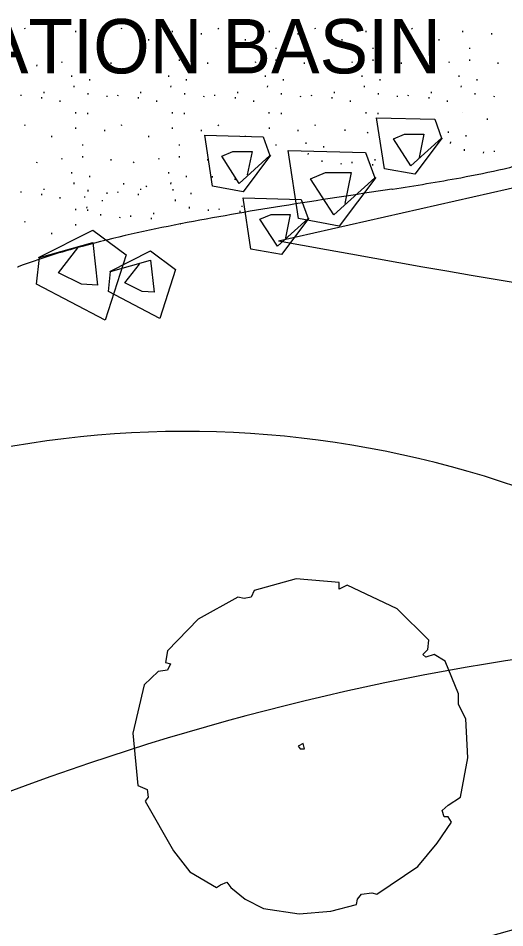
# Model space of a CAD drawing. Extents: x 6712138 to 6712574, y 1869536 to 1870160.
# Drawn here: x 6712324.3 to 6712356.5, y 1869583.4 to 1869643.6 of the extents above; entities that cross this region are included whole.
import ezdxf

# ---------------------------------------------------------------- set-up
doc = ezdxf.new("R2010")
doc.units = 0
for name, color, linetype in [('A-COLS', 7, 'Continuous'), ('A-FLOR-PATT', 7, 'Continuous'), ('A-WALL', 7, 'Continuous'), ('C-Boun', 7, 'Continuous'), ('L-tree', 7, 'Continuous'), ('P-SANR-FIXT', 7, 'Continuous')]:
    doc.layers.add(name, color=color, linetype=linetype)

# ---------------------------------------------------------------- blocks, each defined once
blk = doc.blocks.new('TREE 1')
at = {"layer": 'L-tree'}
for p, q in [((-0.0275, 0.572), (-0.1682, 0.5324)), ((0.1167, 0.5588), (-0.0275, 0.572)), ((0.1167, 0.5368), (0.1167, 0.5588)), ((-0.1682, 0.5324), (-0.1785, 0.5104)), ((0.1441, 0.55), (0.1167, 0.5368)), ((0.3123, 0.4708), (0.1441, 0.55)), ((-0.2231, 0.5104), (-0.357, 0.4356)), ((-0.2025, 0.506), (-0.2231, 0.5104)), ((-0.1785, 0.5104), (-0.2025, 0.506)), ((0.4187, 0.3652), (0.3123, 0.4708)), ((-0.357, 0.4356), (-0.4599, 0.33)), ((0.4153, 0.3344), (0.4187, 0.3652)), ((-0.4599, 0.33), (-0.4668, 0.2904)), ((0.3981, 0.3168), (0.4153, 0.3344)), ((0.4084, 0.308), (0.3981, 0.3168)), ((0.4359, 0.3168), (0.4084, 0.308)), ((0.4737, 0.2948), (0.4359, 0.3168)), ((-0.4668, 0.2904), (-0.4496, 0.286)), ((-0.4496, 0.286), (-0.4599, 0.264)), ((0.5183, 0.1848), (0.4737, 0.2948)), ((-0.4908, 0.2596), (-0.5389, 0.2156)), ((-0.4599, 0.264), (-0.4908, 0.2596)), ((-0.5389, 0.2156), (-0.5766, 0.0528)), ((0.5183, 0.1496), (0.5183, 0.1848)), ((0.5423, 0.1012), (0.5183, 0.1496)), ((0.5492, -0.0308), (0.5423, 0.1012)), ((-0.5766, 0.0528), (-0.5595, -0.1232)), ((-0.0034, 0.0176), (-0.0206, 0.0088)), ((-0.0206, 0.0088), (-0.0137, 0)), ((-0.0137, 0), (0, 0)), ((0, 0), (-0.0034, 0.0176)), ((0.5251, -0.1628), (0.5492, -0.0308)), ((-0.5595, -0.1232), (-0.5286, -0.1364)), ((-0.5286, -0.1364), (-0.5251, -0.1628)), ((-0.5251, -0.1628), (-0.5354, -0.176)), ((-0.5354, -0.176), (-0.4393, -0.3432)), ((0.4839, -0.1892), (0.5251, -0.1628)), ((0.4634, -0.2068), (0.4839, -0.1892)), ((0.4702, -0.2288), (0.4634, -0.2068)), ((0.4839, -0.2288), (0.4702, -0.2288)), ((0.4942, -0.2464), (0.4839, -0.2288)), ((0.4462, -0.3168), (0.4942, -0.2464)), ((0.381, -0.396), (0.4462, -0.3168)), ((-0.4393, -0.3432), (-0.3844, -0.4136)), ((0.2437, -0.4884), (0.381, -0.396)), ((-0.3844, -0.4136), (-0.2952, -0.4664)), ((-0.2952, -0.4664), (-0.2815, -0.4576)), ((-0.2815, -0.4576), (-0.2609, -0.4488)), ((-0.2609, -0.4488), (-0.2471, -0.4664)), ((-0.2471, -0.4664), (-0.1991, -0.506)), ((0.1785, -0.506), (0.1922, -0.4884)), ((0.1922, -0.4884), (0.2265, -0.484)), ((0.2265, -0.484), (0.2437, -0.4884)), ((-0.1991, -0.506), (-0.1373, -0.5368)), ((0.175, -0.5236), (0.1785, -0.506)), ((-0.1373, -0.5368), (-0.0172, -0.5544)), ((-0.0172, -0.5544), (0.0892, -0.5456)), ((0.0892, -0.5456), (0.175, -0.5236))]:
    blk.add_line(p, q, dxfattribs=at)

msp = doc.modelspace()

# ---------------------------------------------------------------- linework, layer by layer
at = {"layer": 'A-FLOR-PATT'}
for p, q in [((6712324.771, 1869642.839), (6712324.742, 1869642.903)), ((6712331.175, 1869642.839), (6712331.146, 1869642.903)), ((6712337.579, 1869642.839), (6712337.55, 1869642.903)), ((6712343.983, 1869642.839), (6712343.954, 1869642.903)), ((6712350.387, 1869642.839), (6712350.358, 1869642.903)), ((6712328.119, 1869642.643), (6712328.119, 1869642.729)), ((6712330.035, 1869642.489), (6712330.035, 1869642.576)), ((6712334.523, 1869642.643), (6712334.523, 1869642.729)), ((6712336.439, 1869642.489), (6712336.439, 1869642.576)), ((6712340.927, 1869642.643), (6712340.927, 1869642.729)), ((6712342.843, 1869642.489), (6712342.843, 1869642.576)), ((6712347.331, 1869642.643), (6712347.331, 1869642.729)), ((6712349.247, 1869642.489), (6712349.247, 1869642.576)), ((6712353.735, 1869642.643), (6712353.735, 1869642.729)), ((6712355.651, 1869642.489), (6712355.651, 1869642.576)), ((6712326.542, 1869642.083), (6712326.542, 1869642.169)), ((6712332.946, 1869642.083), (6712332.946, 1869642.169)), ((6712339.35, 1869642.083), (6712339.35, 1869642.169)), ((6712345.754, 1869642.083), (6712345.754, 1869642.169)), ((6712352.158, 1869642.083), (6712352.158, 1869642.169)), ((6712328.579, 1869641.529), (6712328.579, 1869641.603)), ((6712334.983, 1869641.529), (6712334.983, 1869641.603)), ((6712341.387, 1869641.529), (6712341.387, 1869641.603)), ((6712347.791, 1869641.529), (6712347.791, 1869641.603)), ((6712354.195, 1869641.529), (6712354.195, 1869641.603)), ((6712327.225, 1869640.612), (6712327.199, 1869640.676)), ((6712328.579, 1869640.749), (6712328.579, 1869640.836)), ((6712330.452, 1869640.546), (6712330.452, 1869640.639)), ((6712333.629, 1869640.612), (6712333.603, 1869640.676)), ((6712334.983, 1869640.749), (6712334.983, 1869640.836)), ((6712336.856, 1869640.546), (6712336.856, 1869640.639)), ((6712340.033, 1869640.612), (6712340.007, 1869640.676)), ((6712341.387, 1869640.749), (6712341.387, 1869640.836)), ((6712343.26, 1869640.546), (6712343.26, 1869640.639)), ((6712346.437, 1869640.612), (6712346.411, 1869640.676)), ((6712347.791, 1869640.749), (6712347.791, 1869640.836)), ((6712349.664, 1869640.546), (6712349.664, 1869640.639)), ((6712352.841, 1869640.612), (6712352.815, 1869640.676)), ((6712354.195, 1869640.749), (6712354.195, 1869640.836)), ((6712356.068, 1869640.546), (6712356.068, 1869640.639)), ((6712325.531, 1869640.392), (6712325.568, 1869640.466)), ((6712331.935, 1869640.392), (6712331.972, 1869640.466)), ((6712338.339, 1869640.392), (6712338.376, 1869640.466)), ((6712344.743, 1869640.392), (6712344.78, 1869640.466)), ((6712351.147, 1869640.392), (6712351.184, 1869640.466)), ((6712327.862, 1869639.686), (6712327.862, 1869639.772)), ((6712329.049, 1869639.446), (6712329.049, 1869639.529)), ((6712334.266, 1869639.686), (6712334.266, 1869639.772)), ((6712335.453, 1869639.446), (6712335.453, 1869639.529)), ((6712340.67, 1869639.686), (6712340.67, 1869639.772)), ((6712341.857, 1869639.446), (6712341.857, 1869639.529)), ((6712347.074, 1869639.686), (6712347.074, 1869639.772)), ((6712348.261, 1869639.446), (6712348.261, 1869639.529)), ((6712353.478, 1869639.686), (6712353.478, 1869639.772)), ((6712354.665, 1869639.446), (6712354.665, 1869639.529)), ((6712326.028, 1869638.596), (6712326.028, 1869638.679)), ((6712328.002, 1869638.989), (6712328.019, 1869639.083)), ((6712332.432, 1869638.596), (6712332.432, 1869638.679)), ((6712334.406, 1869638.989), (6712334.423, 1869639.083)), ((6712338.836, 1869638.596), (6712338.836, 1869638.679)), ((6712340.81, 1869638.989), (6712340.827, 1869639.083)), ((6712345.24, 1869638.596), (6712345.24, 1869638.679)), ((6712347.214, 1869638.989), (6712347.231, 1869639.083)), ((6712351.644, 1869638.596), (6712351.644, 1869638.679)), ((6712353.618, 1869638.989), (6712353.635, 1869639.083)), ((6712324.505, 1869638.419), (6712324.515, 1869638.496)), ((6712325.875, 1869638.256), (6712325.875, 1869638.343)), ((6712327.088, 1869638.029), (6712327.088, 1869638.116)), ((6712328.929, 1869638.503), (6712328.929, 1869638.596)), ((6712330.189, 1869638.346), (6712330.199, 1869638.419)), ((6712330.909, 1869638.419), (6712330.919, 1869638.496)), ((6712332.279, 1869638.256), (6712332.279, 1869638.343)), ((6712333.492, 1869638.029), (6712333.492, 1869638.116)), ((6712335.333, 1869638.503), (6712335.333, 1869638.596)), ((6712336.593, 1869638.346), (6712336.603, 1869638.419)), ((6712337.313, 1869638.419), (6712337.323, 1869638.496)), ((6712338.683, 1869638.256), (6712338.683, 1869638.343)), ((6712339.896, 1869638.029), (6712339.896, 1869638.116)), ((6712341.737, 1869638.503), (6712341.737, 1869638.596)), ((6712342.997, 1869638.346), (6712343.007, 1869638.419)), ((6712343.717, 1869638.419), (6712343.727, 1869638.496)), ((6712345.087, 1869638.256), (6712345.087, 1869638.343)), ((6712346.3, 1869638.029), (6712346.3, 1869638.116)), ((6712348.141, 1869638.503), (6712348.141, 1869638.596)), ((6712349.401, 1869638.346), (6712349.411, 1869638.419)), ((6712350.121, 1869638.419), (6712350.131, 1869638.496)), ((6712351.491, 1869638.256), (6712351.491, 1869638.343)), ((6712352.704, 1869638.029), (6712352.704, 1869638.116)), ((6712354.545, 1869638.503), (6712354.545, 1869638.596)), ((6712355.805, 1869638.346), (6712355.815, 1869638.419)), ((6712328.111, 1869637.249), (6712328.111, 1869637.343)), ((6712328.915, 1869637.209), (6712328.915, 1869637.293)), ((6712334.515, 1869637.249), (6712334.515, 1869637.343)), ((6712335.319, 1869637.209), (6712335.319, 1869637.293)), ((6712340.919, 1869637.249), (6712340.919, 1869637.343)), ((6712341.723, 1869637.209), (6712341.723, 1869637.293)), ((6712347.323, 1869637.249), (6712347.323, 1869637.343)), ((6712348.127, 1869637.209), (6712348.127, 1869637.293)), ((6712353.727, 1869637.332), (6712353.727, 1869637.343)), ((6712355.359, 1869636.832), (6712355.359, 1869636.926)), ((6712324.771, 1869636.436), (6712324.742, 1869636.499)), ((6712328.119, 1869636.239), (6712328.119, 1869636.326)), ((6712331.175, 1869636.436), (6712331.146, 1869636.499)), ((6712334.523, 1869636.239), (6712334.523, 1869636.326)), ((6712337.579, 1869636.436), (6712337.55, 1869636.499)), ((6712340.927, 1869636.239), (6712340.927, 1869636.326)), ((6712343.983, 1869636.436), (6712343.954, 1869636.499)), ((6712326.542, 1869635.679), (6712326.542, 1869635.766)), ((6712330.035, 1869636.086), (6712330.035, 1869636.173)), ((6712332.946, 1869635.679), (6712332.946, 1869635.766)), ((6712336.439, 1869636.086), (6712336.439, 1869636.173)), ((6712339.35, 1869635.747), (6712339.35, 1869635.766)), ((6712342.843, 1869636.086), (6712342.843, 1869636.173)), ((6712345.945, 1869636.1), (6712345.945, 1869636.194)), ((6712347.428, 1869635.946), (6712347.465, 1869636.02)), ((6712352.769, 1869635.972), (6712352.769, 1869636.059)), ((6712353.956, 1869635.732), (6712353.956, 1869635.815)), ((6712328.579, 1869635.126), (6712328.579, 1869635.199)), ((6712334.983, 1869635.126), (6712334.983, 1869635.199)), ((6712341.387, 1869635.126), (6712341.387, 1869635.199)), ((6712343.354, 1869635.24), (6712343.354, 1869635.326)), ((6712344.541, 1869635), (6712344.541, 1869635.083)), ((6712352.909, 1869635.275), (6712352.926, 1869635.369)), ((6712343.494, 1869634.543), (6712343.511, 1869634.637)), ((6712353.836, 1869634.789), (6712353.836, 1869634.883)), ((6712355.096, 1869634.632), (6712355.106, 1869634.706)), ((6712355.816, 1869634.706), (6712355.826, 1869634.783)), ((6712325.531, 1869633.989), (6712325.568, 1869634.063)), ((6712327.225, 1869634.209), (6712327.199, 1869634.273)), ((6712328.579, 1869634.346), (6712328.579, 1869634.433)), ((6712330.452, 1869634.143), (6712330.452, 1869634.236)), ((6712331.935, 1869633.989), (6712331.972, 1869634.063)), ((6712333.629, 1869634.209), (6712333.603, 1869634.273)), ((6712334.983, 1869634.346), (6712334.983, 1869634.433)), ((6712336.856, 1869634.143), (6712336.856, 1869634.236)), ((6712344.421, 1869634.057), (6712344.421, 1869634.15)), ((6712345.681, 1869633.9), (6712345.691, 1869633.974)), ((6712346.401, 1869633.974), (6712346.411, 1869634.05)), ((6712347.771, 1869633.81), (6712347.771, 1869633.897)), ((6712347.925, 1869634.15), (6712347.925, 1869634.234)), ((6712327.862, 1869633.283), (6712327.862, 1869633.369)), ((6712334.266, 1869633.283), (6712334.266, 1869633.369)), ((6712328.002, 1869632.586), (6712328.019, 1869632.679)), ((6712329.049, 1869633.043), (6712329.049, 1869633.126)), ((6712334.406, 1869632.586), (6712334.423, 1869632.679)), ((6712335.453, 1869633.043), (6712335.453, 1869633.126)), ((6712337.158, 1869633.014), (6712337.158, 1869633.108)), ((6712338.641, 1869632.861), (6712338.678, 1869632.934)), ((6712324.505, 1869632.016), (6712324.515, 1869632.093)), ((6712326.028, 1869632.193), (6712326.028, 1869632.276)), ((6712328.929, 1869632.099), (6712328.929, 1869632.193)), ((6712330.909, 1869632.016), (6712330.919, 1869632.093)), ((6712331.3, 1869632.543), (6712331.3, 1869632.637)), ((6712332.432, 1869632.193), (6712332.432, 1869632.276)), ((6712332.783, 1869632.39), (6712332.82, 1869632.463)), ((6712334.567, 1869632.154), (6712334.567, 1869632.241)), ((6712325.875, 1869631.853), (6712325.875, 1869631.939)), ((6712327.088, 1869631.626), (6712327.088, 1869631.713)), ((6712328.71, 1869631.683), (6712328.71, 1869631.77)), ((6712329.897, 1869631.443), (6712329.897, 1869631.527)), ((6712330.189, 1869631.943), (6712330.199, 1869632.016)), ((6712332.279, 1869631.853), (6712332.279, 1869631.939)), ((6712334.707, 1869631.457), (6712334.724, 1869631.551)), ((6712335.755, 1869631.914), (6712335.755, 1869631.997)), ((6712328.111, 1869630.846), (6712328.111, 1869630.939)), ((6712328.85, 1869630.987), (6712328.866, 1869631.08)), ((6712328.915, 1869630.806), (6712328.915, 1869630.89)), ((6712335.635, 1869630.971), (6712335.635, 1869631.065)), ((6712336.895, 1869630.814), (6712336.904, 1869630.888)), ((6712337.615, 1869630.888), (6712337.624, 1869630.965)), ((6712339.138, 1869631.065), (6712339.138, 1869631.148)), ((6712329.777, 1869630.5), (6712329.777, 1869630.594)), ((6712331.037, 1869630.343), (6712331.046, 1869630.417)), ((6712331.757, 1869630.417), (6712331.766, 1869630.494)), ((6712333.126, 1869630.254), (6712333.126, 1869630.34)), ((6712333.28, 1869630.594), (6712333.28, 1869630.677)), ((6712338.984, 1869630.725), (6712338.984, 1869630.811)), ((6712324.771, 1869630.033), (6712324.742, 1869630.096)), ((6712328.119, 1869629.836), (6712328.119, 1869629.923)), ((6712326.542, 1869629.276), (6712326.542, 1869629.363))]:
    msp.add_line(p, q, dxfattribs=at)
at = {"layer": 'A-WALL'}
msp.add_line((6712341.53, 1869628.825), (6712401.744, 1869642.44), dxfattribs=at)
for points in [[(6712349.041, 1869632.246), (6712349.056, 1869632.249), (6712349.071, 1869632.251)], [(6712341.755, 1869631.122), (6712341.755, 1869631.122), (6712341.756, 1869631.122)], [(6712335.041, 1869629.942), (6712335.06, 1869629.946), (6712335.08, 1869629.95)], [(6712328.544, 1869628.459), (6712328.547, 1869628.46), (6712328.549, 1869628.46)], [(6712324.261, 1869627.094), (6712324.285, 1869627.103), (6712324.309, 1869627.112)]]:
    msp.add_lwpolyline(points, dxfattribs=at)
for centre, radius, start, end in [((6712342.893, 1869691.98), 59.936, 280.2781, 283.08792), ((6712325.13, 1869789.319), 158.883, 278.66648, 280.31748), ((6712471.986, 1868811.541), 829.863, 98.519821, 99.028752), ((6712374.317, 1869426.076), 207.615, 99.02358, 100.89391), ((6712351.488, 1869542.933), 88.55, 100.70395, 105.01376), ((6712340.958, 1869582.107), 47.986, 104.99258, 110.30174), ((6712573.561, 1870896.65), 1288.883, 259.628794, 261.930335), ((6712335.397, 1869549.11), 67.099, 53.33733, 115.49434), ((6712382.939, 1869434.436), 168.664, 92.54081, 121.99401)]:
    msp.add_arc(centre, radius, start, end, dxfattribs=at)
msp.add_ellipse((6712349.414, 1869664.42), major_axis=(0, -31.627), ratio=0.992455, start_param=0.226556, end_param=0.25056, dxfattribs=at)
at = {"layer": 'C-Boun'}
msp.add_arc((6712717.456, 1868289.472), 1343, 96.709019, 110.149208, dxfattribs=at)
at = {"layer": 'P-SANR-FIXT'}
for points in [[(6712352.366, 1869635.647), (6712350.56, 1869633.229), (6712348.535, 1869633.597), (6712348.026, 1869636.976), (6712351.867, 1869636.873), (6712352.324, 1869635.626), (6712350.288, 1869633.779), (6712349.137, 1869635.578), (6712349.878, 1869635.891), (6712351.144, 1869635.885), (6712350.828, 1869634.348), (6712350.828, 1869634.348)], [(6712341.006, 1869634.49), (6712339.199, 1869632.072), (6712337.175, 1869632.44), (6712336.665, 1869635.819), (6712340.506, 1869635.716), (6712340.963, 1869634.469), (6712338.928, 1869632.622), (6712337.776, 1869634.421), (6712338.517, 1869634.734), (6712339.783, 1869634.728), (6712339.467, 1869633.191), (6712339.467, 1869633.191)], [(6712347.963, 1869633.027), (6712345.555, 1869629.804), (6712342.855, 1869630.295), (6712342.176, 1869634.799), (6712347.297, 1869634.662), (6712347.907, 1869632.999), (6712345.193, 1869630.537), (6712343.658, 1869632.935), (6712344.645, 1869633.353), (6712346.333, 1869633.344), (6712345.913, 1869631.296), (6712345.913, 1869631.296)], [(6712343.535, 1869630.333), (6712341.729, 1869627.915), (6712339.704, 1869628.283), (6712339.195, 1869631.662), (6712343.035, 1869631.559), (6712343.493, 1869630.312), (6712341.457, 1869628.465), (6712340.306, 1869630.264), (6712341.046, 1869630.577), (6712342.312, 1869630.571), (6712341.997, 1869629.034), (6712341.997, 1869629.034)], [(6712325.655, 1869627.715), (6712329.242, 1869629.539), (6712331.445, 1869627.903), (6712330.06, 1869623.564), (6712325.529, 1869625.954), (6712325.718, 1869627.715), (6712329.242, 1869628.721), (6712329.556, 1869625.891), (6712328.486, 1869625.954), (6712326.976, 1869626.708), (6712328.26, 1869628.359), (6712328.26, 1869628.359)], [(6712330.379, 1869626.791), (6712333.069, 1869628.159), (6712334.721, 1869626.933), (6712333.683, 1869623.678), (6712330.284, 1869625.47), (6712330.426, 1869626.791), (6712333.069, 1869627.546), (6712333.305, 1869625.423), (6712332.502, 1869625.47), (6712331.37, 1869626.036), (6712332.333, 1869627.274), (6712332.333, 1869627.274)]]:
    msp.add_lwpolyline(points, dxfattribs=at)

# ---------------------------------------------------------------- block references
at = {"layer": 'L-tree', "xscale": 19.685038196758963, "yscale": 19.685039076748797}
msp.add_blockref('TREE 1', (6712343.241, 1869595.199), dxfattribs=at)

# ---------------------------------------------------------------- texts
at = {"layer": 'A-COLS'}
msp.add_text('INFILTRATION BASIN', height=3.6, dxfattribs=at).set_placement((6712303.593, 1869639.908))

doc.saveas('drawing.dxf')
